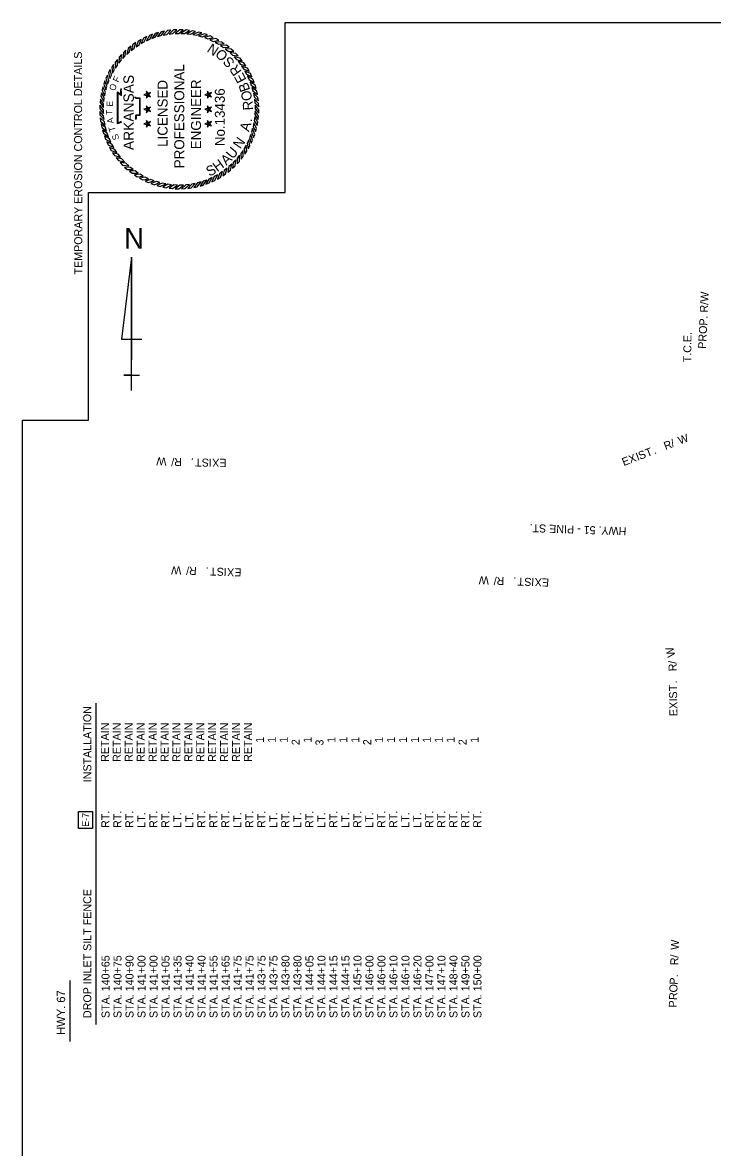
# Model space of a CAD drawing. Extents: x 991974 to 993016, y 1842702 to 1844298.
# Drawn here: x 991974 to 992492, y 1843454 to 1844298 of the extents above; entities that cross this region are included whole.
import ezdxf

# ---------------------------------------------------------------- set-up
doc = ezdxf.new("R2010")
doc.units = 0
for name, color, linetype in [('1', 7, 'Continuous'), ('44', 7, 'Continuous'), ('63', 7, 'Continuous'), ('Default', 7, 'Continuous'), ('G-ANNO-SYMB', 7, 'Continuous'), ('G-ANNO-TEXT', 7, 'Continuous'), ('R_Draft', 7, 'Continuous')]:
    doc.layers.add(name, color=color, linetype=linetype)

msp = doc.modelspace()

# ---------------------------------------------------------------- linework, layer by layer
at = {"layer": '1'}
msp.add_lwpolyline([(992016.13, 1843693.44), (992016.13, 1843706.19), (992026.64, 1843706.19), (992026.64, 1843693.44)], close=True, dxfattribs=at)
at = {"layer": '44'}
for p, q in [((992029.39, 1843546.4), (992029.39, 1843787.4)), ((992009.8, 1843533.71), (992009.8, 1843579.29))]:
    msp.add_line(p, q, dxfattribs=at)
at = {"layer": '63'}
for p, q in [((992055.91, 1844121.85), (992048.22, 1844060.32)), ((992055.91, 1844021.85), (992055.91, 1844121.85)), ((992055.91, 1844121.85), (992055.91, 1844044.93)), ((992048.22, 1844060.32), (992063.61, 1844060.32)), ((992055.91, 1844021.85), (992055.91, 1844044.93)), ((992055.91, 1844033.39), (992050.14, 1844033.39)), ((992050.14, 1844033.39), (992061.68, 1844033.39)), ((992055.91, 1844021.85), (992055.91, 1844033.39))]:
    msp.add_line(p, q, dxfattribs=at)
at = {"layer": 'Default'}
msp.add_lwpolyline([(993016.34, 1842702.47), (991974.02, 1842702.47), (991974.02, 1843999.48), (992023.57, 1843999.48), (992023.57, 1844170.33), (992171.07, 1844170.33), (992171.07, 1844297.83), (993016.34, 1844297.83)], close=True, dxfattribs=at)
msp.add_lwpolyline([(993016.34, 1842702.47), (991974.02, 1842702.47), (991974.02, 1843999.48), (992023.57, 1843999.48), (992023.57, 1844170.33), (992171.07, 1844170.33), (992171.07, 1844297.83), (993016.34, 1844297.83)], close=True, dxfattribs=at)
at = {"layer": 'G-ANNO-SYMB'}
for points in [[(992071.57, 1844288.96), (992069.17, 1844288.05), (992066.92, 1844284.07), (992069.45, 1844285.21)], [(992076.04, 1844290.36), (992073.58, 1844289.64), (992071.02, 1844285.85), (992073.63, 1844286.79)], [(992080.61, 1844291.41), (992078.1, 1844290.88), (992075.25, 1844287.3), (992077.92, 1844288.03)], [(992085.24, 1844292.09), (992082.7, 1844291.76), (992079.58, 1844288.42), (992082.3, 1844288.94)], [(992089.92, 1844292.41), (992087.35, 1844292.28), (992083.98, 1844289.19), (992086.74, 1844289.49)], [(992094.6, 1844292.36), (992092.03, 1844292.43), (992088.43, 1844289.61), (992091.2, 1844289.7)], [(992099.27, 1844291.94), (992096.71, 1844292.21), (992092.9, 1844289.69), (992095.67, 1844289.56)], [(992103.88, 1844291.16), (992101.36, 1844291.63), (992097.36, 1844289.41), (992100.11, 1844289.07)], [(992108.43, 1844290.01), (992105.95, 1844290.68), (992101.79, 1844288.79), (992104.5, 1844288.23)], [(992112.87, 1844288.52), (992110.45, 1844289.38), (992106.15, 1844287.82), (992108.81, 1844287.05)], [(992117.17, 1844286.68), (992114.83, 1844287.73), (992110.43, 1844286.51), (992113.02, 1844285.53)], [(992055.19, 1844280.02), (992053.19, 1844278.41), (992052.28, 1844273.92), (992054.33, 1844275.79)], [(992059.01, 1844282.73), (992056.89, 1844281.28), (992055.63, 1844276.88), (992057.82, 1844278.58)], [(992063.03, 1844285.13), (992060.8, 1844283.86), (992059.2, 1844279.57), (992061.52, 1844281.09)], [(992067.22, 1844287.21), (992064.91, 1844286.12), (992062.97, 1844281.97), (992065.4, 1844283.31)], [(992121.33, 1844284.51), (992119.07, 1844285.74), (992114.59, 1844284.87), (992117.09, 1844283.69)], [(992125.29, 1844282.02), (992123.14, 1844283.42), (992118.6, 1844282.9), (992121.01, 1844281.53)], [(992129.05, 1844279.23), (992127.02, 1844280.79), (992122.45, 1844280.63), (992124.74, 1844279.08)], [(992048.25, 1844273.73), (992046.53, 1844271.83), (992046.33, 1844267.26), (992048.06, 1844269.43)], [(992051.59, 1844277.01), (992049.73, 1844275.25), (992049.17, 1844270.71), (992051.07, 1844272.73)], [(992132.58, 1844276.15), (992130.68, 1844277.87), (992126.11, 1844278.07), (992128.28, 1844276.33)], [(992135.86, 1844272.8), (992134.1, 1844274.66), (992129.56, 1844275.22), (992131.58, 1844273.32)], [(992138.86, 1844269.2), (992137.25, 1844271.2), (992132.77, 1844272.11), (992134.64, 1844270.06)], [(992039.88, 1844262.48), (992038.65, 1844260.23), (992039.53, 1844255.74), (992040.7, 1844258.24)], [(992042.37, 1844266.44), (992040.97, 1844264.3), (992041.49, 1844259.75), (992042.86, 1844262.16)], [(992045.17, 1844270.2), (992043.6, 1844268.17), (992043.76, 1844263.6), (992045.32, 1844265.9)], [(992141.58, 1844265.38), (992140.13, 1844267.5), (992135.73, 1844268.76), (992137.43, 1844266.57)], [(992143.98, 1844261.36), (992142.7, 1844263.59), (992138.42, 1844265.19), (992139.94, 1844262.87)], [(992035.87, 1844254.02), (992035.01, 1844251.6), (992036.57, 1844247.3), (992037.35, 1844249.97)], [(992037.71, 1844258.33), (992036.66, 1844255.98), (992037.88, 1844251.58), (992038.86, 1844254.17)], [(992146.06, 1844257.17), (992144.96, 1844259.49), (992140.82, 1844261.42), (992142.16, 1844258.99)], [(992147.81, 1844252.82), (992146.9, 1844255.22), (992142.92, 1844257.47), (992144.06, 1844254.94)], [(992034.38, 1844249.58), (992033.71, 1844247.1), (992035.6, 1844242.94), (992036.17, 1844245.65)], [(992067.86, 1844243.68), (992068.19, 1844244.67), (992067.02, 1844246.27), (992067.02, 1844244.29)], [(992067.86, 1844243.68), (992068.91, 1844243.68), (992070.07, 1844245.28), (992068.19, 1844244.67)], [(992113.55, 1844243.68), (992113.87, 1844244.67), (992112.7, 1844246.27), (992112.7, 1844244.29)], [(992113.55, 1844243.68), (992114.59, 1844243.68), (992115.75, 1844245.28), (992113.87, 1844244.67)], [(992149.21, 1844248.35), (992148.49, 1844250.81), (992144.7, 1844253.37), (992145.64, 1844250.76)], [(992150.25, 1844243.78), (992149.73, 1844246.3), (992146.15, 1844249.14), (992146.88, 1844246.47)], [(992032.45, 1844240.42), (992032.18, 1844237.87), (992034.7, 1844234.05), (992034.83, 1844236.82)], [(992033.23, 1844245.04), (992032.76, 1844242.51), (992034.98, 1844238.51), (992035.33, 1844241.26)], [(992067.86, 1844243.68), (992067.02, 1844244.29), (992065.14, 1844243.68), (992067.02, 1844243.07)], [(992067.86, 1844243.68), (992067.02, 1844243.07), (992067.02, 1844241.09), (992068.19, 1844242.69)], [(992067.86, 1844243.68), (992068.19, 1844242.69), (992070.07, 1844242.08), (992068.91, 1844243.68)], [(992113.55, 1844243.68), (992112.7, 1844244.29), (992110.82, 1844243.68), (992112.7, 1844243.07)], [(992113.55, 1844243.68), (992112.7, 1844243.07), (992112.7, 1844241.09), (992113.87, 1844242.69)], [(992113.55, 1844243.68), (992113.87, 1844242.69), (992115.75, 1844242.08), (992114.59, 1844243.68)], [(992150.94, 1844239.15), (992150.61, 1844241.69), (992147.26, 1844244.81), (992147.78, 1844242.09)], [(992151.26, 1844234.48), (992151.13, 1844237.04), (992148.04, 1844240.41), (992148.34, 1844237.66)], [(992032.04, 1844235.75), (992031.96, 1844233.19), (992034.78, 1844229.58), (992034.69, 1844232.35)], [(992031.99, 1844231.07), (992032.11, 1844228.5), (992035.2, 1844225.13), (992034.9, 1844227.89)], [(992067.86, 1844232.77), (992067.02, 1844233.38), (992065.14, 1844232.77), (992067.02, 1844232.16)], [(992067.86, 1844232.77), (992068.19, 1844233.76), (992067.02, 1844235.37), (992067.02, 1844233.38)], [(992067.86, 1844232.77), (992067.02, 1844232.16), (992067.02, 1844230.18), (992068.19, 1844231.78)], [(992067.86, 1844232.77), (992068.91, 1844232.77), (992070.07, 1844234.37), (992068.19, 1844233.76)], [(992067.86, 1844232.77), (992068.19, 1844231.78), (992070.07, 1844231.17), (992068.91, 1844232.77)], [(992113.55, 1844232.77), (992112.7, 1844233.38), (992110.82, 1844232.77), (992112.7, 1844232.16)], [(992113.55, 1844232.77), (992113.87, 1844233.76), (992112.7, 1844235.37), (992112.7, 1844233.38)], [(992113.55, 1844232.77), (992112.7, 1844232.16), (992112.7, 1844230.18), (992113.87, 1844231.78)], [(992113.55, 1844232.77), (992114.59, 1844232.77), (992115.75, 1844234.37), (992113.87, 1844233.76)], [(992113.55, 1844232.77), (992113.87, 1844231.78), (992115.75, 1844231.17), (992114.59, 1844232.77)], [(992150.79, 1844225.13), (992151.06, 1844227.68), (992148.54, 1844231.49), (992148.41, 1844228.72)], [(992151.21, 1844229.79), (992151.28, 1844232.36), (992148.46, 1844235.96), (992148.55, 1844233.19)], [(992032.3, 1844226.39), (992032.63, 1844223.85), (992035.98, 1844220.73), (992035.46, 1844223.45)], [(992032.99, 1844221.76), (992033.51, 1844219.25), (992037.09, 1844216.4), (992036.36, 1844219.07)], [(992067.86, 1844221.86), (992067.02, 1844222.47), (992065.14, 1844221.86), (992067.02, 1844221.25)], [(992067.86, 1844221.86), (992068.19, 1844222.85), (992067.02, 1844224.46), (992067.02, 1844222.47)], [(992067.86, 1844221.86), (992067.02, 1844221.25), (992067.02, 1844219.27), (992068.19, 1844220.87)], [(992067.86, 1844221.86), (992068.91, 1844221.86), (992070.07, 1844223.47), (992068.19, 1844222.85)], [(992067.86, 1844221.86), (992068.19, 1844220.87), (992070.07, 1844220.26), (992068.91, 1844221.86)], [(992113.55, 1844221.86), (992112.7, 1844222.47), (992110.82, 1844221.86), (992112.7, 1844221.25)], [(992113.55, 1844221.86), (992113.87, 1844222.85), (992112.7, 1844224.46), (992112.7, 1844222.47)], [(992113.55, 1844221.86), (992112.7, 1844221.25), (992112.7, 1844219.27), (992113.87, 1844220.87)], [(992113.55, 1844221.86), (992114.59, 1844221.86), (992115.75, 1844223.47), (992113.87, 1844222.85)], [(992113.55, 1844221.86), (992113.87, 1844220.87), (992115.75, 1844220.26), (992114.59, 1844221.86)], [(992148.86, 1844215.97), (992149.53, 1844218.44), (992147.64, 1844222.6), (992147.08, 1844219.89)], [(992150.01, 1844220.51), (992150.48, 1844223.03), (992148.26, 1844227.03), (992147.92, 1844224.28)], [(992034.03, 1844217.19), (992034.75, 1844214.73), (992038.54, 1844212.17), (992037.61, 1844214.78)], [(992035.43, 1844212.72), (992036.34, 1844210.32), (992040.32, 1844208.07), (992039.18, 1844210.6)], [(992145.53, 1844207.22), (992146.58, 1844209.56), (992145.36, 1844213.96), (992144.38, 1844211.37)], [(992147.37, 1844211.53), (992148.23, 1844213.94), (992146.67, 1844218.24), (992145.89, 1844215.58)], [(992037.18, 1844208.38), (992038.28, 1844206.06), (992042.42, 1844204.12), (992041.08, 1844206.55)], [(992039.26, 1844204.18), (992040.54, 1844201.95), (992044.82, 1844200.35), (992043.3, 1844202.67)], [(992140.87, 1844199.1), (992142.27, 1844201.25), (992141.75, 1844205.79), (992140.38, 1844203.38)], [(992143.36, 1844203.07), (992144.59, 1844205.32), (992143.72, 1844209.81), (992142.54, 1844207.3)], [(992041.66, 1844200.16), (992043.11, 1844198.04), (992047.51, 1844196.78), (992045.81, 1844198.97)], [(992044.38, 1844196.34), (992045.99, 1844194.34), (992050.47, 1844193.43), (992048.6, 1844195.48)], [(992131.65, 1844188.53), (992133.51, 1844190.29), (992134.07, 1844194.83), (992132.17, 1844192.81)], [(992134.99, 1844191.81), (992136.72, 1844193.71), (992136.91, 1844198.28), (992135.18, 1844196.12)], [(992138.07, 1844195.34), (992139.64, 1844197.37), (992139.48, 1844201.94), (992137.92, 1844199.65)], [(992047.38, 1844192.75), (992049.14, 1844190.88), (992053.68, 1844190.32), (992051.66, 1844192.22)], [(992050.66, 1844189.4), (992052.56, 1844187.68), (992057.13, 1844187.48), (992054.96, 1844189.21)], [(992054.19, 1844186.32), (992056.22, 1844184.75), (992060.79, 1844184.91), (992058.5, 1844186.47)], [(992124.23, 1844182.82), (992126.35, 1844184.26), (992127.61, 1844188.66), (992125.42, 1844186.96)], [(992128.05, 1844185.53), (992130.05, 1844187.14), (992130.96, 1844191.62), (992128.91, 1844189.75)], [(992057.95, 1844183.52), (992060.1, 1844182.12), (992064.64, 1844182.64), (992062.23, 1844184.01)], [(992061.91, 1844181.03), (992064.17, 1844179.8), (992068.66, 1844180.68), (992066.15, 1844181.86)], [(992066.07, 1844178.86), (992068.41, 1844177.81), (992072.81, 1844179.04), (992070.22, 1844180.01)], [(992070.37, 1844177.02), (992072.79, 1844176.16), (992077.09, 1844177.73), (992074.43, 1844178.5)], [(992102.63, 1844174.14), (992105.14, 1844174.67), (992107.99, 1844178.24), (992105.32, 1844177.51)], [(992107.2, 1844175.18), (992109.66, 1844175.91), (992112.22, 1844179.7), (992109.61, 1844178.76)], [(992111.67, 1844176.58), (992114.07, 1844177.5), (992116.32, 1844181.48), (992113.79, 1844180.33)], [(992116.02, 1844178.33), (992118.34, 1844179.43), (992120.27, 1844183.57), (992117.84, 1844182.24)], [(992120.21, 1844180.41), (992122.44, 1844181.69), (992124.04, 1844185.97), (992121.72, 1844184.45)], [(992074.81, 1844175.53), (992077.29, 1844174.86), (992081.45, 1844176.76), (992078.74, 1844177.32)], [(992079.36, 1844174.39), (992081.88, 1844173.91), (992085.88, 1844176.13), (992083.13, 1844176.48)], [(992083.98, 1844173.6), (992086.53, 1844173.33), (992090.34, 1844175.85), (992087.57, 1844175.98)], [(992088.64, 1844173.19), (992091.21, 1844173.11), (992094.81, 1844175.93), (992092.04, 1844175.84)], [(992093.33, 1844173.14), (992095.89, 1844173.27), (992099.26, 1844176.35), (992096.5, 1844176.05)], [(992098, 1844173.45), (992100.54, 1844173.78), (992103.66, 1844177.13), (992100.94, 1844176.61)]]:
    msp.add_lwpolyline(points, close=True, dxfattribs=at)
for points in [[(992048.32, 1844223.21), (992045.31, 1844221.82), (992045.29, 1844245.89), (992047.82, 1844243.88), (992047.8, 1844245.51), (992047.78, 1844246.88), (992047.93, 1844248.24)], [(992048.16, 1844223.56), (992045.69, 1844222.42), (992045.68, 1844245.1), (992048.21, 1844243.08), (992048.18, 1844245.52), (992048.16, 1844246.86), (992048.31, 1844248.2)], [(992058.11, 1844241.85), (992058.52, 1844241.35), (992059.17, 1844241.17), (992060.46, 1844241.03), (992061.77, 1844241.03), (992061.77, 1844228.36), (992059.9, 1844228.36), (992059.12, 1844228.36), (992058.86, 1844227.49), (992058.86, 1844225.73), (992058.51, 1844225.5)], [(992058.4, 1844242.09), (992058.74, 1844241.68), (992059.24, 1844241.55), (992060.49, 1844241.41), (992062.15, 1844241.41), (992062.15, 1844227.98), (992059.9, 1844227.98), (992059.4, 1844227.98), (992059.24, 1844227.43), (992059.24, 1844225.52), (992058.72, 1844225.18)]]:
    msp.add_lwpolyline(points, dxfattribs=at)

# ---------------------------------------------------------------- texts
at = {"layer": '1'}
msp.add_text('E-7 ', height=4.999, rotation=89.61324, dxfattribs=at).set_placement((992023.82, 1843694.6))
at = {"layer": '44'}
for s, height, p in [('INSTALLATION', 6, (992025.63, 1843728.04)), ('RT.', 6, (992039.16, 1843693.76)), ('RT.', 6, (992048.16, 1843693.76)), ('RT.', 6, (992057.16, 1843693.76)), ('RT.', 6, (992192.16, 1843693.76)), ('RT.', 6, (992210.16, 1843693.76)), ('RT.', 6, (992228.16, 1843693.76)), ('RT.', 6, (992246.16, 1843693.76)), ('RT.', 6, (992255.16, 1843693.76)), ('RT.', 6, (992282.16, 1843693.76)), ('RT.', 6, (992291.16, 1843693.76)), ('RT.', 6, (992300.16, 1843693.76)), ('RT.', 6, (992309.16, 1843693.76)), ('RT.', 6, (992318.16, 1843693.76)), ('LT.', 6, (992138.16, 1843693.9)), ('LT.', 6, (992165.16, 1843693.9)), ('LT.', 6, (992183.16, 1843693.9)), ('LT.', 6, (992201.16, 1843693.9)), ('LT.', 6, (992219.16, 1843693.9)), ('LT.', 6, (992237.16, 1843693.9)), ('LT.', 6, (992264.16, 1843693.9)), ('LT.', 6, (992273.16, 1843693.9)), ('DROP INLET SILT FENCE', 6, (992025.63, 1843551.19)), ('HWY. 67', 6.25, (992006.02, 1843538.56))]:
    msp.add_text(s, height=height, rotation=90, dxfattribs=at).set_placement(p)
at = {"layer": '63'}
msp.add_text('N', height=15.38, rotation=0, dxfattribs=at).set_placement((992050.28, 1844128.26))
at = {"layer": 'G-ANNO-SYMB'}
for s, height, rotation, p in [('N', 7.5, 146.10067, (992122.05, 1844278.51)), ('O', 7.5, 134.77573, (992128.81, 1844273.3)), ('S', 7.5, 133.48784, (992133.78, 1844268.15)), ('PROFESSIONAL', 7.5, 90, (992095.37, 1844188.49)), ('R', 7.5, 125.65967, (992138.88, 1844261.25)), ('F', 4.75, 65.36282, (992045.86, 1844252.61)), ('ARKANSAS', 7.747, 90, (992057.54, 1844202.15)), ('LICENSED', 7.5, 90, (992082.83, 1844204.56)), ('ENGINEER', 7.5, 90, (992107.91, 1844202.77)), ('E', 7.5, 117.83149, (992142.2, 1844254.91)), ('O', 4.75, 71.2218, (992043.35, 1844246.21)), ('No.13436', 7.47, 90, (992125.79, 1844205.14)), ('B', 7.5, 108.88501, (992144.91, 1844247.34)), ('O', 7.5, 101.42961, (992146.5, 1844239.82)), ('E', 4.75, 86.67203, (992041.73, 1844234.68)), ('R', 7.5, 93.22866, (992146.99, 1844232.15)), ('T', 4.75, 91.47887, (992041.58, 1844228.61)), ('A', 4.75, 98.67877, (992042.53, 1844222.48)), ('A', 7.5, 73.09908, (992143.85, 1844215.58)), ('.', 7.5, 81.30002, (992146.04, 1844222.95)), ('T', 4.75, 106.90148, (992044.03, 1844216.72)), ('S', 4.75, 109.77256, (992046.74, 1844210.68)), ('N', 7.5, 54.93262, (992137.42, 1844202.51)), ('U', 7.5, 50.90262, (992131.83, 1844194.95)), ('H', 7.5, 35.61905, (992120.1, 1844185.51)), ('A', 7.5, 43.44722, (992126.94, 1844190.27)), ('S', 7.5, 28.16364, (992114.22, 1844182.09))]:
    msp.add_text(s, height=height, rotation=rotation, dxfattribs=at).set_placement(p)
at = {"layer": 'G-ANNO-TEXT'}
msp.add_text('TEMPORARY EROSION CONTROL DETAILS', height=6, rotation=90.07909, dxfattribs=at).set_placement((992018.89, 1844108.85))
at = {"layer": 'R_Draft'}
for s, rotation, p in [('PROP. R/W', 87.28268, (992486.79, 1844053.02)), ('T.C.E.', 89.40901, (992475.66, 1844042.97)), ('R', 20.9463, (992456.42, 1843977.16)), ('/', 20.9463, (992461.71, 1843979.19)), ('W', 20.9463, (992467.19, 1843981.28)), ('I', 20.9463, (992435.46, 1843969.14)), ('S', 20.9463, (992437.32, 1843969.85)), ('T', 20.9463, (992442.61, 1843971.88)), ('.', 20.9463, (992448.08, 1843973.97)), ('W', 178.24464, (992082.11, 1843971.49)), ('/', 178.24464, (992087.97, 1843971.31)), ('R', 178.24464, (992093.64, 1843971.13)), ('.', 178.24464, (992102.56, 1843970.86)), ('T', 179.30223, (992108.31, 1843970.81)), ('S', 179.30223, (992113.98, 1843970.74)), ('I', 179.30223, (992115.96, 1843970.72)), ('X', 179.30223, (992121.72, 1843970.65)), ('E', 179.30223, (992127.11, 1843970.58)), ('E', 20.9463, (992425.05, 1843965.15)), ('X', 20.9463, (992430.08, 1843967.08)), ('HWY. 51 - PINE ST.', 178.05575, (992427.13, 1843919.22)), ('W', 178.15992, (992093.27, 1843889.83)), ('/', 178.15992, (992099.12, 1843889.65)), ('R', 178.15992, (992104.79, 1843889.46)), ('.', 178.15992, (992113.71, 1843889.18)), ('T', 178.15992, (992119.57, 1843888.99)), ('S', 178.15992, (992125.24, 1843888.81)), ('I', 178.15992, (992127.22, 1843888.74)), ('X', 178.15992, (992132.98, 1843888.56)), ('E', 178.15992, (992138.36, 1843888.38)), ('W', 178.05575, (992324, 1843882.29)), ('/', 178.05575, (992329.86, 1843882.1)), ('R', 178.05575, (992335.52, 1843881.9)), ('.', 178.05575, (992344.45, 1843881.6)), ('T', 178.05575, (992350.3, 1843881.4)), ('S', 178.05575, (992355.97, 1843881.21)), ('I', 178.05575, (992357.95, 1843881.14)), ('X', 178.05575, (992363.71, 1843880.95)), ('E', 178.05575, (992369.1, 1843880.76)), ('W', 104.91415, (992463.85, 1843822.71)), ('/', 91.02618, (992464.63, 1843816.94)), ('R', 91.02618, (992464.73, 1843811.28)), ('T', 91.02618, (992465, 1843796.49)), ('.', 91.02618, (992464.89, 1843802.35)), ('S', 91.02618, (992465.1, 1843790.82)), ('I', 91.02618, (992465.14, 1843788.84)), ('X', 91.02618, (992465.24, 1843783.08)), ('E', 91.02618, (992465.34, 1843777.69)), ('RETAIN', 89.99998, (992038.81, 1843743.35)), ('RETAIN', 89.99998, (992047.76, 1843743.35)), ('RETAIN', 89.99998, (992056.71, 1843743.35)), ('RETAIN', 89.99998, (992065.66, 1843743.35)), ('RETAIN', 89.99998, (992074.61, 1843743.35)), ('RETAIN', 89.99998, (992083.56, 1843743.35)), ('RETAIN', 89.99998, (992092.5, 1843743.35)), ('RETAIN', 89.99998, (992101.4, 1843743.35)), ('RETAIN', 89.99998, (992110.35, 1843743.35)), ('RETAIN', 89.99998, (992119.3, 1843743.35)), ('RETAIN', 89.99998, (992128.25, 1843743.35)), ('RETAIN', 89.99998, (992137.2, 1843743.35)), ('RETAIN', 89.99998, (992146.14, 1843743.35)), ('1', 89.99998, (992155.09, 1843757.6)), ('1', 89.99998, (992164.04, 1843757.6)), ('1', 89.99998, (992172.99, 1843757.6)), ('2', 89.99998, (992181.94, 1843755.89)), ('1', 89.99998, (992190.83, 1843757.6)), ('3', 89.99998, (992199.78, 1843755.59)), ('1', 89.99998, (992208.73, 1843757.6)), ('1', 89.99998, (992217.68, 1843757.6)), ('1', 89.99998, (992226.63, 1843757.6)), ('2', 89.99998, (992235.58, 1843755.89)), ('1', 89.99998, (992244.52, 1843757.6)), ('1', 89.99998, (992253.47, 1843757.6)), ('1', 89.99998, (992262.42, 1843757.6)), ('1', 89.99998, (992271.37, 1843757.6)), ('1', 89.99998, (992280.32, 1843757.6)), ('1', 89.99998, (992289.27, 1843757.6)), ('1', 89.99998, (992298.21, 1843757.6)), ('2', 89.99998, (992307.16, 1843755.89)), ('1', 89.99998, (992316.11, 1843757.6)), ('RT.', 90, (992075.16, 1843693.76)), ('RT.', 90, (992084.16, 1843693.76)), ('RT.', 90, (992111.16, 1843693.76)), ('RT.', 90, (992120.16, 1843693.76)), ('RT.', 90, (992129.16, 1843693.76)), ('RT.', 90, (992147.16, 1843693.76)), ('RT.', 90, (992156.16, 1843693.76)), ('RT.', 90, (992174.16, 1843693.76)), ('LT.', 90, (992066.16, 1843693.9)), ('LT.', 90, (992093.16, 1843693.9)), ('LT.', 90, (992102.16, 1843693.9)), ('W', 88.03611, (992466.3, 1843602.26)), ('STA. 140+65', 90, (992039.31, 1843551.19)), ('STA. 140+75', 90, (992048.31, 1843551.19)), ('STA. 140+90', 90, (992057.31, 1843551.19)), ('STA. 141+00', 90, (992066.31, 1843551.19)), ('STA. 141+00', 90, (992075.31, 1843551.19)), ('STA. 141+05', 90, (992084.31, 1843551.19)), ('STA. 141+35', 90, (992093.31, 1843551.19)), ('STA. 141+40', 90, (992102.31, 1843551.19)), ('STA. 141+40', 90, (992111.31, 1843551.19)), ('STA. 141+55', 90, (992120.31, 1843551.19)), ('STA. 141+65', 90, (992129.31, 1843551.19)), ('STA. 141+75', 90, (992138.31, 1843551.19)), ('STA. 141+75', 90, (992147.31, 1843551.19)), ('STA. 143+75', 90, (992156.31, 1843551.19)), ('STA. 143+75', 90, (992165.31, 1843551.19)), ('STA. 143+80', 90, (992174.31, 1843551.19)), ('STA. 143+80', 90, (992183.3, 1843551.19)), ('STA. 144+05', 90, (992192.3, 1843551.19)), ('STA. 144+10', 90, (992201.3, 1843551.19)), ('STA. 144+15', 90, (992210.3, 1843551.19)), ('STA. 144+15', 90, (992219.3, 1843551.19)), ('STA. 145+10', 90, (992228.3, 1843551.19)), ('STA. 146+00', 90, (992237.3, 1843551.19)), ('STA. 146+00', 90, (992246.3, 1843551.19)), ('STA. 146+10', 90, (992255.3, 1843551.19)), ('STA. 146+10', 90, (992264.3, 1843551.19)), ('STA. 146+20', 90, (992273.3, 1843551.19)), ('STA. 147+00', 90, (992282.3, 1843551.19)), ('STA. 147+10', 90, (992291.3, 1843551.19)), ('STA. 148+40', 90, (992300.3, 1843551.19)), ('STA. 149+50', 90, (992309.3, 1843551.19)), ('STA. 150+00', 90, (992318.3, 1843551.19)), ('/', 88.03611, (992466.09, 1843596.41)), ('R', 88.03611, (992465.9, 1843590.74)), ('P', 88.03611, (992465.4, 1843576.15)), ('.', 88.03611, (992465.59, 1843581.82)), ('O', 88.03611, (992465.2, 1843570.3)), ('P', 88.03611, (992464.81, 1843558.97)), ('R', 88.03611, (992465.01, 1843564.63))]:
    msp.add_text(s, height=6, rotation=rotation, dxfattribs=at).set_placement(p)

doc.saveas('drawing.dxf')
